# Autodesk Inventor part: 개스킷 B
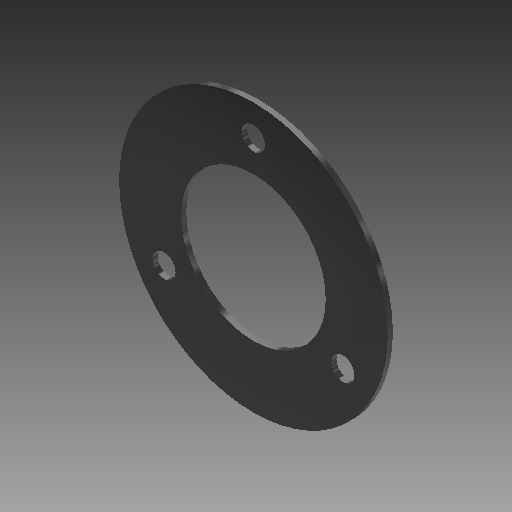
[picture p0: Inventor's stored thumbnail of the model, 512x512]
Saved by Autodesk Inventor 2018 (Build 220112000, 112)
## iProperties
Created: 2020-04
Part Number: 개스킷 B
Material: 고무
Document SubType Name: Modeling
Designer: mduedu
Density: 0.93 g/cm^3
Mass: 1.35803 g
Surface Area: 32.1424 cm^2
Volume: 1.46025 cm^3
Appearance: 고무 - 검은색 - 버전 1.1
Author: mduedu
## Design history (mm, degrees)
sketch "스케치1"
  geometry: C1 r 26 at (0, 0); 1 further point
  constraints: 1 centre point, 1 coincident
  dimensions: "d0" = 52 diameter of C1
extrude "돌출1" new body sketch "스케치1" distance "d1" = 1; taper "d2" = 0 deg
sketch "스케치3" dims "d6" = 40
  geometry: 3 further points
  constraints: 2 vertical alignment, 1 coincident, 2 other
hole "구멍1" sketch "스케치3" at (0, 20) diameter "d7" = 4.5; stored, may be unused: countersink angle "d11" = 90 deg, drill point angle "d13" = 118 deg; dims "d8" = 6, "d9" = 4, "d10" = 2, "d12" = 8
sketch "스케치4"
  geometry: C1 r 14 at (0, 0); 1 further point
  constraints: 1 centre point, 1 coincident
  dimensions: "d17" = 28 diameter of C1
extrude "돌출3" cut sketch "스케치4" extent not by distance; stored distance "d18" = 1; taper "d19" = 0 deg
node "솔리드1"
pattern_circular "원형 패턴1" dims angle "d15" = 360 deg
